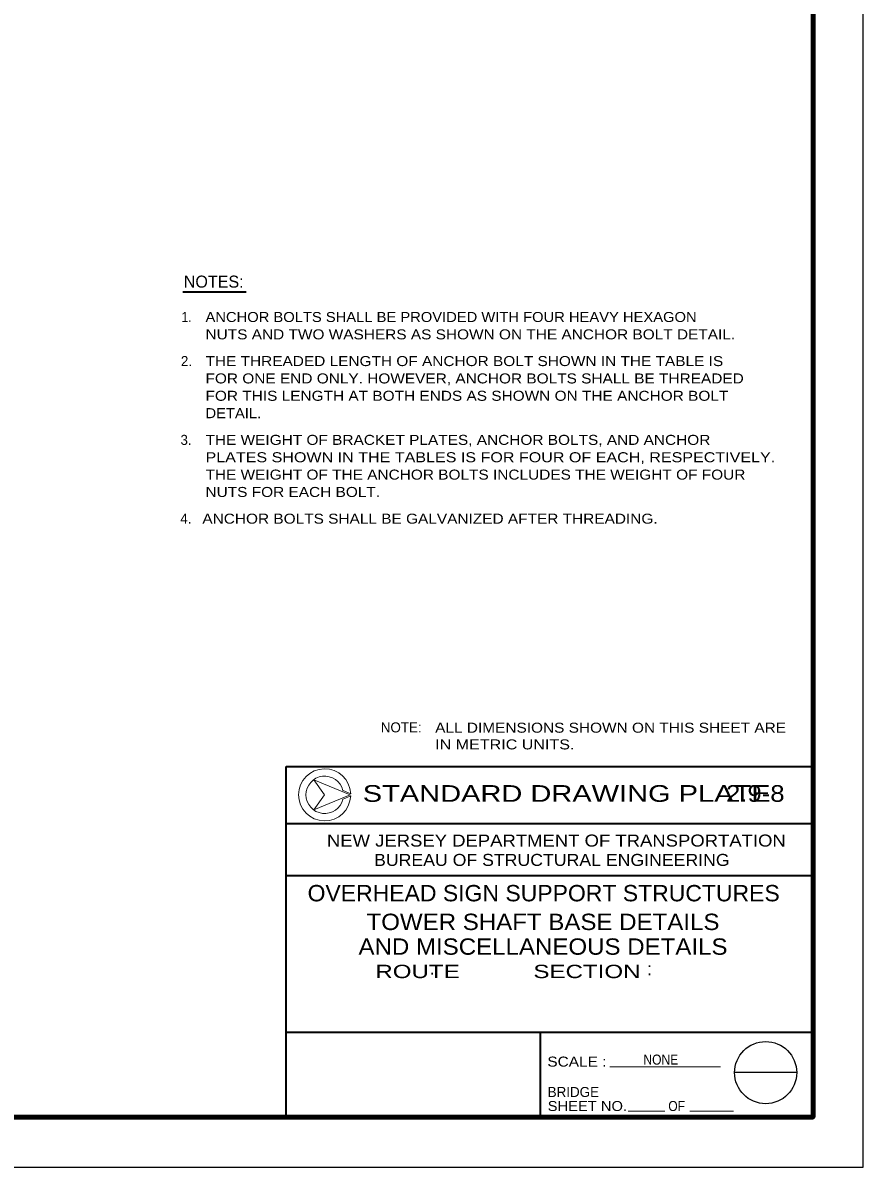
# Model space of a CAD drawing. Extents: x 312601.859 to 312602.7, y 144420.109 to 144420.704.
# Drawn here: x 312602.4486 to 312602.7003, y 144420.1095 to 144420.4522 of the extents above; entities that cross this region are included whole.
import ezdxf
from ezdxf.enums import TextEntityAlignment as Align

# ---------------------------------------------------------------- set-up
doc = ezdxf.new("R2010")
doc.units = 0
doc.header["$LTSCALE"] = 0.0012
for name, color, linetype, lineweight in [('1', 7, 'Continuous', 13), ('2', 7, 'Continuous', 13), ('39', 7, 'Continuous', 13)]:
    doc.layers.add(name, color=color, linetype=linetype, lineweight=lineweight)
doc.layers.add('4', color=7, linetype='Continuous')

msp = doc.modelspace()

# ---------------------------------------------------------------- linework, layer by layer
at = {"layer": '1'}
msp.add_line((312602.5445, 144420.2197), (312602.5468, 144420.2207), dxfattribs=at)
for points in [[(312602.5466, 144420.221), (312602.5357, 144420.2255), (312602.5466, 144420.221)], [(312602.5468, 144420.2213), (312602.5445, 144420.2223), (312602.5444, 144420.2223)]]:
    msp.add_lwpolyline(points, dxfattribs=at)
for points in [[(312602.5466, 144420.221), (312602.5357, 144420.2255), (312602.5389, 144420.221), (312602.5357, 144420.2165)], [(312602.5389, 144420.221), (312602.5357, 144420.2165), (312602.5466, 144420.221), (312602.5357, 144420.2255)]]:
    msp.add_lwpolyline(points, close=True, dxfattribs=at)
for radius, start, end in [(0.0078026, 2.21392, 357.78608), (0.0056, 13.69411, 346.30589)]:
    msp.add_arc((312602.539, 144420.221), radius, start, end, dxfattribs=at)
at = {"layer": '2', "lineweight": 35}
msp.add_line((312602.4965, 144420.3716), (312602.5155, 144420.3716), dxfattribs=at)
at = {"layer": '39', "lineweight": 35}
for p, q in [((312602.5275, 144420.1245), (312602.5275, 144420.2295)), ((312602.5275, 144420.2295), (312602.6853, 144420.2295)), ((312602.6853, 144420.2295), (312602.6853, 144420.1245)), ((312602.5275, 144420.2124), (312602.6853, 144420.2124)), ((312602.5275, 144420.1968), (312602.6853, 144420.1968)), ((312602.5275, 144420.1499), (312602.6853, 144420.1499)), ((312602.6037, 144420.1248), (312602.6037, 144420.1499))]:
    msp.add_line(p, q, dxfattribs=at)
at = {"layer": '39'}
for p, q in [((312602.6037, 144420.1499), (312602.6853, 144420.1499)), ((312602.6037, 144420.1248), (312602.6037, 144420.1499)), ((312602.6037, 144420.1248), (312602.6037, 144420.1499)), ((312602.6244, 144420.1395), (312602.6576, 144420.1395)), ((312602.6299, 144420.1263), (312602.6409, 144420.1263)), ((312602.6484, 144420.1263), (312602.6615, 144420.1263))]:
    msp.add_line(p, q, dxfattribs=at)
at = {"layer": '39', "lineweight": 25}
for p, q in [((312602.6804, 144420.1378), (312602.6618, 144420.1378)), ((312602.4535, 144420.1245), (312602.6853, 144420.1245))]:
    msp.add_line(p, q, dxfattribs=at)
msp.add_lwpolyline([(312601.8593, 144420.1095), (312602.7003, 144420.1095), (312602.7003, 144420.7035)], dxfattribs=at)
at = {"layer": '39', "lineweight": 158}
msp.add_lwpolyline([(312601.9103, 144420.1245), (312602.6853, 144420.1245), (312602.6853, 144420.6645)], dxfattribs=at)
at = {"layer": '39'}
msp.add_lwpolyline([(312602.5466, 144420.221), (312602.5357, 144420.2255), (312602.5389, 144420.221), (312602.5357, 144420.2165)], close=True, dxfattribs=at)
at = {"layer": '39', "lineweight": 25}
msp.add_circle((312602.6711, 144420.1378), 0.0093005, dxfattribs=at)

# ---------------------------------------------------------------- texts
at = {"layer": '2'}
for s, height, p in [('NOTES:', 0.0036, (312602.50575, 144420.3729)), ('2.', 0.003, (312602.4976, 144420.3494)), ('4.', 0.003, (312602.4974, 144420.3022))]:
    msp.add_text(s, height=height, dxfattribs=at).set_placement(p, align=Align.CENTER)
for s, width, p in [('1.', 0.9, (312602.4961, 144420.3626)), ('ANCHOR BOLTS SHALL BE PROVIDED WITH FOUR HEAVY HEXAGON', 1.1, (312602.5033, 144420.3626)), ('NUTS AND TWO WASHERS AS SHOWN ON THE ANCHOR BOLT DETAIL.', 1.15, (312602.5033, 144420.3574)), ('THE THREADED LENGTH OF ANCHOR BOLT SHOWN IN THE TABLE IS', 1.15, (312602.5033, 144420.3494)), ('FOR ONE END ONLY. HOWEVER, ANCHOR BOLTS SHALL BE THREADED', 1.15, (312602.5033, 144420.3442)), ('FOR THIS LENGTH AT BOTH ENDS AS SHOWN ON THE ANCHOR BOLT', 1.15, (312602.5033, 144420.339)), ('DETAIL.', 1.1, (312602.5033, 144420.3338)), ('THE WEIGHT OF BRACKET PLATES, ANCHOR BOLTS, AND ANCHOR ', 1.15, (312602.5033, 144420.3258)), ('PLATES SHOWN IN THE TABLES IS FOR FOUR OF EACH, RESPECTIVELY.', 1.2, (312602.5033, 144420.3206)), ('THE WEIGHT OF THE ANCHOR BOLTS INCLUDES THE WEIGHT OF FOUR', 1.15, (312602.5033, 144420.3154)), ('NUTS FOR EACH BOLT.', 1.15, (312602.5033, 144420.3102))]:
    msp.add_text(s, height=0.003, dxfattribs=dict(at, width=width)).set_placement(p)
msp.add_text('3.', height=0.003, dxfattribs=at).set_placement((312602.4958, 144420.3258))
for s, height, width, p in [('ANCHOR BOLTS SHALL BE GALVANIZED AFTER THREADING.', 0.003, 1.15, (312602.57055, 144420.3022)), ('2.9-8', 0.005, 1.15, (312602.668, 144420.2189)), ('OVERHEAD SIGN SUPPORT STRUCTURES', 0.0049, 1.05, (312602.6046, 144420.1891)), ('TOWER SHAFT BASE DETAILS', 0.0049, 1.1, (312602.6044, 144420.1805)), ('AND MISCELLANEOUS DETAILS', 0.0049, 1.1, (312602.6044, 144420.1731)), ('NONE', 0.003, 0.9, (312602.6397, 144420.1402))]:
    msp.add_text(s, height=height, dxfattribs=dict(at, width=width)).set_placement(p, align=Align.CENTER)
at = {"layer": '39'}
for s, height, width, p in [('STANDARD DRAWING PLATE       ', 0.005, 1.3, (312602.61995, 144420.2189)), ('NEW JERSEY DEPARTMENT OF TRANSPORTATION', 0.003599, 1.15, (312602.6084, 144420.2055)), ('BUREAU OF STRUCTURAL ENGINEERING', 0.0036, 1.1, (312602.60705, 144420.1997)), ('ROUTE           SECTION', 0.004, 1.35, (312602.5939, 144420.1661)), ('SCALE :', 0.003, 1.15, (312602.61455, 144420.1396)), ('OF', 0.003, 0.9, (312602.64445, 144420.1263))]:
    msp.add_text(s, height=height, dxfattribs=dict(at, width=width)).set_placement(p, align=Align.CENTER)
for p in [(312602.571237, 144420.1671), (312602.636337, 144420.1669)]:
    msp.add_text(':', height=0.004, dxfattribs=at).set_placement(p, align=Align.CENTER)
msp.add_text('BRIDGE', height=0.003, dxfattribs=at).set_placement((312602.6058, 144420.1305))
at = {"layer": '39', "width": 1.1}
msp.add_text('SHEET NO.', height=0.003, dxfattribs=at).set_placement((312602.6058, 144420.1263))
at = {"layer": '4'}
msp.add_text('NOTE:', height=0.003, dxfattribs=at).set_placement((312602.5558, 144420.2397))
for s, width, p in [('ALL DIMENSIONS SHOWN ON THIS SHEET ARE', 1.15, (312602.5721, 144420.2396)), ('IN METRIC UNITS.', 1.2, (312602.5721, 144420.2346))]:
    msp.add_text(s, height=0.003, dxfattribs=dict(at, width=width)).set_placement(p)

doc.saveas('drawing.dxf')
